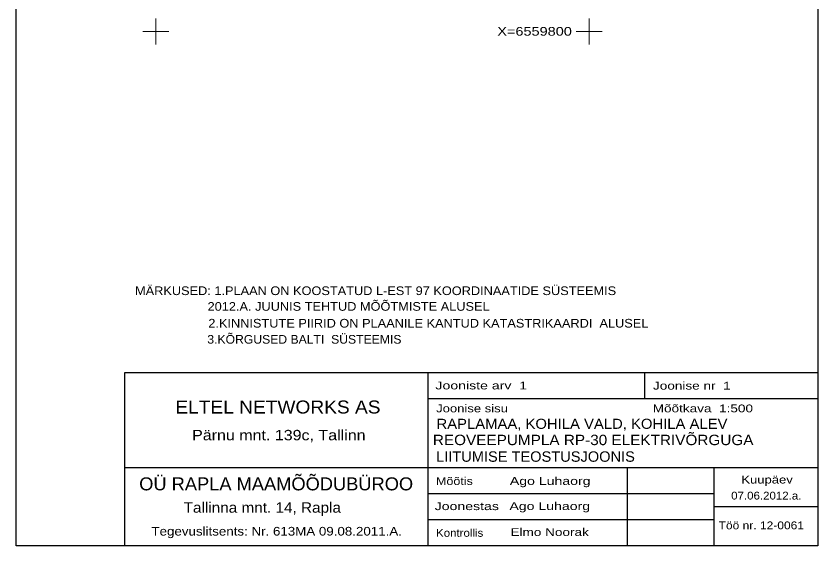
# Model space of a CAD drawing. Extents: x 543034 to 543126, y 6559741 to 6559884.
# Drawn here: x 543033.9 to 543126.4, y 6559740.6 to 6559801.8 of the extents above; entities that cross this region are included whole.
import ezdxf
from ezdxf.enums import TextEntityAlignment as Align

# ---------------------------------------------------------------- set-up
doc = ezdxf.new("R2010")
doc.units = 0
doc.header["$LTSCALE"] = 0.36
doc.layers.add('58', color=7, linetype='Continuous', lineweight=25)
doc.layers.add('63', color=7, linetype='Continuous', lineweight=13)

msp = doc.modelspace()

# ---------------------------------------------------------------- linework, layer by layer
at = {"layer": '58'}
for p, q in [((543046.39, 6559760.6), (543046.39, 6559740.6)), ((543081.39, 6559760.6), (543081.39, 6559740.6)), ((543081.39, 6559760.6), (543081.39, 6559740.6)), ((543106.39, 6559760.6), (543106.39, 6559757.6)), ((543126.39, 6559760.6), (543126.39, 6559740.6)), ((543126.39, 6559757.6), (543081.39, 6559757.6)), ((543126.39, 6559749.6), (543046.39, 6559749.6)), ((543104.39, 6559749.6), (543104.39, 6559740.6)), ((543114.39, 6559749.6), (543114.39, 6559740.6)), ((543114.39, 6559746.6), (543081.39, 6559746.6)), ((543126.39, 6559745.1), (543114.39, 6559745.1)), ((543114.39, 6559743.6), (543081.39, 6559743.6)), ((543126.39, 6559740.6), (543046.39, 6559740.6))]:
    msp.add_line(p, q, dxfattribs=at)
msp.add_lwpolyline([(543033.89, 6559884.1), (543126.39, 6559884.1), (543126.39, 6559740.6), (543033.89, 6559740.6)], close=True, dxfattribs=at)
msp.add_lwpolyline([(543126.39, 6559760.6), (543046.39, 6559760.6), (543046.39, 6559740.6)], dxfattribs=at)
at = {"layer": '63'}
for p, q in [((543050, 6559801.5), (543050, 6559798.5)), ((543100, 6559801.5), (543100, 6559798.5)), ((543048.5, 6559800), (543051.5, 6559800)), ((543098.5, 6559800), (543101.5, 6559800))]:
    msp.add_line(p, q, dxfattribs=at)

# ---------------------------------------------------------------- texts
at = {"layer": '58'}
for s, height, width, p in [('MÄRKUSED: 1.PLAAN ON KOOSTATUD L-EST 97 KOORDINAATIDE SÜSTEEMIS', 1, 1.1, (543075.365, 6559769.56)), ('2012.A. JUUNIS TEHTUD MÕÕTMISTE ALUSEL', 1, 1.1, (543072.25, 6559767.75)), ('2.KINNISTUTE PIIRID ON PLAANILE KANTUD KATASTRIKAARDI  ALUSEL', 1, 1.1, (543081.45, 6559765.81)), ('3.KÕRGUSED BALTI  SÜSTEEMIS', 1, 1.05, (543067.15, 6559763.95)), ('ELTEL NETWORKS AS', 1.5, 1.1, (543064.1, 6559755.89)), ('RAPLAMAA, KOHILA VALD, KOHILA ALEV', 1.163, 1.1, (543099.17, 6559754.12)), ('Pärnu mnt. 139c, Tallinn', 1.2, 1.15, (543064.205, 6559752.8)), ('REOVEEPUMPLA RP-30 ELEKTRIVÕRGUGA', 1.2, 1.1, (543100.46, 6559752.24)), ('LIITUMISE TEOSTUSJOONIS', 1.2, 1.05, (543093.805, 6559750.32)), ('OÜ RAPLA MAAMÕÕDUBÜROO', 1.5, 1.05, (543063.895, 6559747.02)), ('Tegevuslitsents: Nr. 613MA 09.08.2011.A.', 1, 1.15, (543063.955, 6559741.8))]:
    msp.add_text(s, height=height, dxfattribs=dict(at, width=width)).set_placement(p, align=Align.CENTER)
for s, height, width, p in [('Jooniste arv  1', 0.9, 1.35, (543082.27, 6559758.67)), ('Joonise nr  1', 0.9, 1.3, (543107.36, 6559758.65)), ('Joonise sisu', 0.9, 1.25, (543082.35, 6559756.03)), ('Mõõtkava  1:500', 0.9, 1.3, (543107.33, 6559756.03)), ('Mõõtis', 0.9, 1.2, (543082.33, 6559747.64)), ('Ago Luhaorg', 0.9, 1.35, (543090.85, 6559747.65)), ('Kuupäev', 0.9, 1.25, (543117.55, 6559747.81)), ('07.06.2012.a.', 0.9, 1.1, (543116.38, 6559745.96)), ('Tallinna mnt. 14, Rapla', 1.2, 1.1, (543053.22, 6559744.44)), ('Joonestas', 0.9, 1.35, (543082.18, 6559744.74)), ('Ago Luhaorg', 0.9, 1.35, (543090.8, 6559744.75)), ('Töö nr. 12-0061', 0.9, 1.15, (543114.93, 6559742.53)), ('Kontrollis', 0.9, 1.1, (543082.34, 6559741.66)), ('Elmo Noorak', 0.9, 1.3, (543090.92, 6559741.75))]:
    msp.add_text(s, height=height, dxfattribs=dict(at, width=width)).set_placement(p)
at = {"layer": '63', "width": 1.25}
msp.add_text('X=6559800', height=1, dxfattribs=at).set_placement((543098, 6559799.5), align=Align.RIGHT)

doc.saveas('drawing.dxf')
